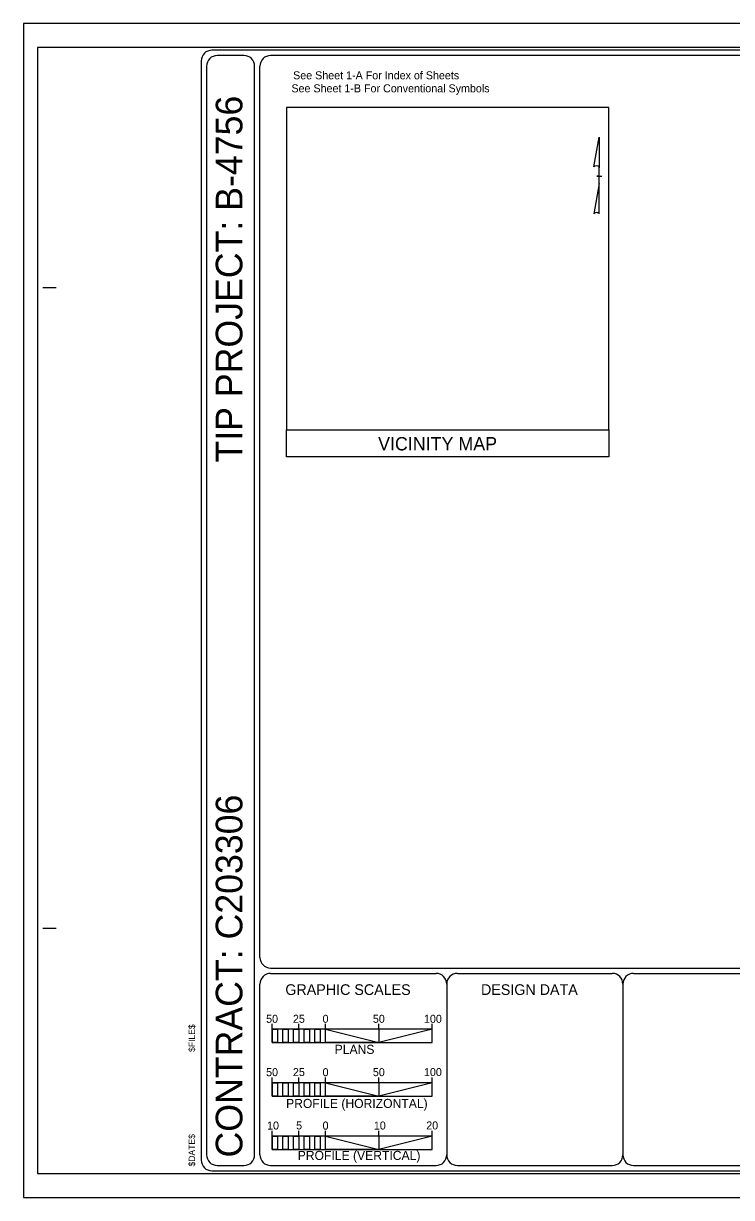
# Model space of a CAD drawing. Extents: x 2431000 to 2534000, y 645879 to 714000.
# Drawn here: x 2463853 to 2464516, y 678900 to 680000 of the extents above; entities that cross this region are included whole.
import ezdxf

# ---------------------------------------------------------------- set-up
doc = ezdxf.new("R2010")
doc.units = 0
for name, color, linetype in [('Prop Dimension Text', 7, 'Continuous'), ('Prop North Arrow for Plan Sheets CELL', 7, 'Continuous'), ('Sheet Plot Border Inside CELL', 7, 'Continuous'), ('Sheet Plot Border Outside CELL', 7, 'Continuous'), ('Sheet Title CELL', 7, 'Continuous')]:
    doc.layers.add(name, color=color, linetype=linetype)

msp = doc.modelspace()

# ---------------------------------------------------------------- linework, layer by layer
at = {"layer": 'Prop Dimension Text'}
for p, q in [((2464401.6, 679921.4), (2464099.6, 679921.4)), ((2464099.6, 679921.4), (2464099.6, 679619.4)), ((2464401.6, 679619.4), (2464401.6, 679921.4)), ((2464099.6, 679619.4), (2464401.6, 679619.4))]:
    msp.add_line(p, q, dxfattribs=at)
msp.add_lwpolyline([(2464401.6, 679594), (2464099.6, 679594), (2464099.6, 679619.4), (2464401.6, 679619.4)], close=True, dxfattribs=at)
at = {"layer": 'Prop North Arrow for Plan Sheets CELL'}
for p, q in [((2464387.6, 679865.8), (2464392.6, 679893.6)), ((2464392.6, 679893.6), (2464392.6, 679893.6)), ((2464392.6, 679893.6), (2464392.6, 679893.6)), ((2464392.6, 679893.6), (2464392.6, 679864.9)), ((2464390.2, 679857), (2464395, 679857)), ((2464392.3, 679857), (2464390.2, 679857)), ((2464390.2, 679857), (2464390.2, 679857)), ((2464392.6, 679850.1), (2464392.6, 679865.8)), ((2464392.6, 679864.9), (2464392.6, 679865.8)), ((2464392.6, 679850.1), (2464387.6, 679821.7)), ((2464392.6, 679821.8), (2464392.6, 679850.1))]:
    msp.add_line(p, q, dxfattribs=at)
for centre, start_param, end_param in [((2464390.1, 679865.5), 0.216388, 2.908219), ((2464390.1, 679821.6), 0.201328, 3.141593)]:
    msp.add_ellipse(centre, major_axis=(2.54, -0.02), ratio=0.461098, start_param=start_param, end_param=end_param, dxfattribs=at)
at = {"layer": 'Sheet Plot Border Inside CELL'}
msp.add_lwpolyline([(2463866.2, 678922.5), (2465532.2, 678922.5), (2465532.2, 679977.5), (2463866.2, 679977.5)], close=True, dxfattribs=at)
at = {"layer": 'Sheet Plot Border Outside CELL'}
msp.add_lwpolyline([(2463853.2, 678900), (2465536.7, 678900), (2465536.7, 680000), (2463853.2, 680000)], close=True, dxfattribs=at)
at = {"layer": 'Sheet Title CELL'}
for p, q in [((2464069.7, 678940), (2464069.7, 679960)), ((2464074.7, 679125), (2464074.7, 679960)), ((2463871.2, 679752.5), (2463883.7, 679752.5)), ((2463871.2, 679752.5), (2463883.7, 679752.5)), ((2463871.2, 679152.5), (2463883.7, 679152.5)), ((2463871.2, 679152.5), (2463883.7, 679152.5)), ((2464084.7, 679115), (2465504.7, 679115)), ((2464084.7, 679110), (2464239.7, 679110)), ((2464259.7, 679110), (2464404.7, 679110)), ((2464424.7, 679110), (2464804.7, 679110)), ((2464074.7, 678940), (2464074.7, 679100)), ((2464249.7, 679100), (2464249.7, 678940)), ((2464414.7, 679100), (2464414.7, 678940)), ((2464086.2, 679057.6), (2464086.2, 679062.6)), ((2464086.2, 679062.6), (2464086.2, 679062.6)), ((2464086.2, 679057.6), (2464086.2, 679045.1)), ((2464086.2, 679057.6), (2464086.2, 679057.6)), ((2464236.2, 679057.6), (2464086.2, 679057.6)), ((2464111.2, 679057.6), (2464111.2, 679062.6)), ((2464121.2, 679057.6), (2464121.2, 679045.1)), ((2464136.2, 679057.6), (2464136.2, 679062.6)), ((2464186.2, 679057.6), (2464186.2, 679062.6)), ((2464186.2, 679057.6), (2464186.2, 679045.1)), ((2464236.2, 679057.6), (2464236.2, 679062.6)), ((2464236.2, 679045.1), (2464236.2, 679057.6)), ((2464086.2, 679045.1), (2464236.2, 679045.1)), ((2464086.2, 679007.6), (2464086.2, 679012.6)), ((2464086.2, 679007.6), (2464086.2, 679012.6)), ((2464086.2, 679012.6), (2464086.2, 679012.6)), ((2464111.2, 679007.6), (2464111.2, 679012.6)), ((2464111.2, 679007.6), (2464111.2, 679012.6)), ((2464136.2, 679007.6), (2464136.2, 679012.6)), ((2464136.2, 679007.6), (2464136.2, 679012.6)), ((2464186.2, 679007.6), (2464186.2, 679012.6)), ((2464186.2, 679007.6), (2464186.2, 679012.6)), ((2464236.2, 679007.6), (2464236.2, 679012.6)), ((2464236.2, 679007.6), (2464236.2, 679012.6)), ((2464086.2, 679007.6), (2464086.2, 678995.1)), ((2464086.2, 679007.6), (2464086.2, 679007.6)), ((2464236.2, 679007.6), (2464086.2, 679007.6)), ((2464086.2, 679007.6), (2464086.2, 679007.6)), ((2464236.2, 679007.6), (2464086.2, 679007.6)), ((2464121.2, 679007.6), (2464121.2, 678995.1)), ((2464186.2, 679007.6), (2464186.2, 678995.1)), ((2464236.2, 678995.1), (2464236.2, 679007.6)), ((2464086.2, 678995.1), (2464236.2, 678995.1)), ((2464086.2, 678957.6), (2464086.2, 678962.6)), ((2464086.2, 678957.6), (2464086.2, 678962.6)), ((2464086.2, 678957.6), (2464086.2, 678962.6)), ((2464086.2, 678962.6), (2464086.2, 678962.6)), ((2464086.2, 678957.6), (2464086.2, 678945.1)), ((2464086.2, 678957.6), (2464086.2, 678957.6)), ((2464236.2, 678957.6), (2464086.2, 678957.6)), ((2464086.2, 678957.6), (2464086.2, 678957.6)), ((2464236.2, 678957.6), (2464086.2, 678957.6)), ((2464086.2, 678957.6), (2464086.2, 678957.6)), ((2464236.2, 678957.6), (2464086.2, 678957.6)), ((2464111.2, 678957.6), (2464111.2, 678962.6)), ((2464111.2, 678957.6), (2464111.2, 678962.6)), ((2464111.2, 678957.6), (2464111.2, 678962.6)), ((2464121.2, 678957.6), (2464121.2, 678945.1)), ((2464136.2, 678957.6), (2464136.2, 678962.6)), ((2464136.2, 678957.6), (2464136.2, 678962.6)), ((2464136.2, 678957.6), (2464136.2, 678962.6)), ((2464186.2, 678957.6), (2464186.2, 678962.6)), ((2464186.2, 678957.6), (2464186.2, 678962.6)), ((2464186.2, 678957.6), (2464186.2, 678962.6)), ((2464186.2, 678957.6), (2464186.2, 678945.1)), ((2464236.2, 678957.6), (2464236.2, 678962.6)), ((2464236.2, 678957.6), (2464236.2, 678962.6)), ((2464236.2, 678957.6), (2464236.2, 678962.6)), ((2464236.2, 678945.1), (2464236.2, 678957.6)), ((2464086.2, 678945.1), (2464236.2, 678945.1)), ((2464019.7, 678925), (2464019.7, 678925)), ((2464019.7, 678925), (2464019.7, 678925)), ((2464019.7, 678925), (2464019.7, 678925)), ((2464019.7, 678925), (2464019.7, 678925))]:
    msp.add_line(p, q, dxfattribs=at)
for points in [[(2465509.7, 679975), (2464029.7, 679975)], [(2464059.7, 679970), (2464034.7, 679970)], [(2465504.7, 679970), (2464084.7, 679970)], [(2464019.7, 679965), (2464019.7, 678935)], [(2464019.7, 679965), (2464019.7, 678935)], [(2464024.7, 679960), (2464024.7, 678940)], [(2464029.7, 678925), (2465509.7, 678925)], [(2464034.7, 678930), (2464059.7, 678930)], [(2464084.7, 678930), (2464239.7, 678930)], [(2464259.7, 678930), (2464404.7, 678930)], [(2464424.7, 678930), (2464804.7, 678930)]]:
    msp.add_lwpolyline(points, dxfattribs=at)
for points in [[(2464086.2, 679057.6), (2464091.2, 679057.6), (2464091.2, 679045.1), (2464086.2, 679045.1)], [(2464096.2, 679057.6), (2464101.2, 679057.6), (2464101.2, 679045.1), (2464096.2, 679045.1)], [(2464106.2, 679057.6), (2464111.2, 679057.6), (2464111.2, 679045.1), (2464106.2, 679045.1)], [(2464116.2, 679057.6), (2464121.2, 679057.6), (2464121.2, 679045.1), (2464116.2, 679045.1)], [(2464126.2, 679057.6), (2464131.2, 679057.6), (2464131.2, 679045.1), (2464126.2, 679045.1)], [(2464136.2, 679057.6), (2464186.2, 679045.1), (2464136.2, 679045.1)], [(2464236.2, 679057.6), (2464186.2, 679045.1), (2464236.2, 679045.1)], [(2464086.2, 679007.6), (2464091.2, 679007.6), (2464091.2, 678995.1), (2464086.2, 678995.1)], [(2464096.2, 679007.6), (2464101.2, 679007.6), (2464101.2, 678995.1), (2464096.2, 678995.1)], [(2464106.2, 679007.6), (2464111.2, 679007.6), (2464111.2, 678995.1), (2464106.2, 678995.1)], [(2464116.2, 679007.6), (2464121.2, 679007.6), (2464121.2, 678995.1), (2464116.2, 678995.1)], [(2464126.2, 679007.6), (2464131.2, 679007.6), (2464131.2, 678995.1), (2464126.2, 678995.1)], [(2464136.2, 679007.6), (2464186.2, 678995.1), (2464136.2, 678995.1)], [(2464236.2, 679007.6), (2464186.2, 678995.1), (2464236.2, 678995.1)], [(2464086.2, 678957.6), (2464091.2, 678957.6), (2464091.2, 678945.1), (2464086.2, 678945.1)], [(2464096.2, 678957.6), (2464101.2, 678957.6), (2464101.2, 678945.1), (2464096.2, 678945.1)], [(2464106.2, 678957.6), (2464111.2, 678957.6), (2464111.2, 678945.1), (2464106.2, 678945.1)], [(2464116.2, 678957.6), (2464121.2, 678957.6), (2464121.2, 678945.1), (2464116.2, 678945.1)], [(2464126.2, 678957.6), (2464131.2, 678957.6), (2464131.2, 678945.1), (2464126.2, 678945.1)], [(2464136.2, 678957.6), (2464186.2, 678945.1), (2464136.2, 678945.1)], [(2464236.2, 678957.6), (2464186.2, 678945.1), (2464236.2, 678945.1)]]:
    msp.add_lwpolyline(points, close=True, dxfattribs=at)
for centre, start, end in [((2464029.7, 679965), 90, 180), ((2464034.7, 679960), 90, 180), ((2464059.7, 679960), 0, 90), ((2464084.7, 679960), 90, 180), ((2464084.7, 679125), 180, 270), ((2464084.7, 679100), 90, 180), ((2464239.7, 679100), 0, 90), ((2464259.7, 679100), 90, 180), ((2464404.7, 679100), 0, 90), ((2464424.7, 679100), 90, 180), ((2464029.7, 678935), 180, 270), ((2464034.7, 678940), 180, 270), ((2464059.7, 678940), 270, 0), ((2464084.7, 678940), 180, 270), ((2464239.7, 678940), 270, 0), ((2464259.7, 678940), 180, 270), ((2464404.7, 678940), 270, 0), ((2464424.7, 678940), 180, 270)]:
    msp.add_arc(centre, 10, start, end, dxfattribs=at)

# ---------------------------------------------------------------- texts
at = {"layer": 'Prop Dimension Text'}
msp.add_text('VICINITY MAP', height=12.5, dxfattribs=at).set_placement((2464185.4, 679600))
at = {"layer": 'Sheet Title CELL'}
for s, height, p in [('See Sheet 1-A For Index of Sheets', 7.5, (2464105.8, 679947.7)), ('See Sheet 1-B For Conventional Symbols', 7.5, (2464104.2, 679935.5)), ('GRAPHIC SCALES', 10, (2464098.5, 679089.8)), ('DESIGN DATA', 10, (2464281.8, 679089.8)), ('50', 7.5, (2464080.5, 679063.7)), ('25', 7.5, (2464105.6, 679063.7)), ('0', 7.5, (2464133.4, 679063.7)), ('50', 7.5, (2464180.5, 679063.7)), ('100', 7.5, (2464228.4, 679063.7)), ('PLANS', 8.5, (2464144.7, 679034.6)), ('50', 7.5, (2464080.5, 679013.7)), ('25', 7.5, (2464105.6, 679013.8)), ('0', 7.5, (2464133.4, 679013.7)), ('0', 7.5, (2464133.4, 679013.6)), ('50', 7.5, (2464180.5, 679013.7)), ('100', 7.5, (2464228.4, 679013.8)), ('PROFILE (HORIZONTAL)', 8.5, (2464099.2, 678983.9)), ('10', 7.5, (2464081.4, 678963.7)), ('5', 7.5, (2464108.6, 678963.8)), ('0', 7.5, (2464133.4, 678963.7)), ('0', 7.5, (2464133.4, 678963.6)), ('0', 7.5, (2464133.4, 678963.6)), ('10', 7.5, (2464181.4, 678963.7)), ('20', 7.5, (2464230.5, 678963.8)), ('PROFILE (VERTICAL)', 8.5, (2464110.1, 678935.2))]:
    msp.add_text(s, height=height, dxfattribs=at).set_placement(p)
for s, height, p in [('TIP PROJECT: B-4756', 25, (2464058.3, 679588.6)), ('CONTRACT: C203306', 25, (2464058.3, 678937.5)), ('$FILE$', 6, (2464013.9, 679036.4)), ('$DATE$', 6, (2464013.9, 678929.1))]:
    msp.add_text(s, height=height, rotation=90, dxfattribs=at).set_placement(p)

doc.saveas('drawing.dxf')
